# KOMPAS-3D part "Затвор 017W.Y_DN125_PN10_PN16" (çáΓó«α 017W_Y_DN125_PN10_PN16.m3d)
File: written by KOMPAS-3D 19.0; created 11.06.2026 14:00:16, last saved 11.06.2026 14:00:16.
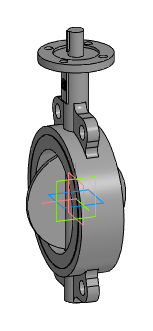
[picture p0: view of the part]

Document properties: Автор: Евгений; Полное имя файла: Z:\3.Личные\kachalov\001_3d для проектировщиков\x.x Тип 017W.Y(S) Затвор дисковый поворотный межфланцевый\_stp_Затвор 017W.Y_DN50-DN350\Затвор 017W_Y_DN125_PN10_PN16.m3d

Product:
- Part/product: Затвор 017W.Y_DN125_PN10_PN16

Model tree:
1. Операция без истории:1  (labels: Затвор 017W.Y_DN125_PN10_PN16)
